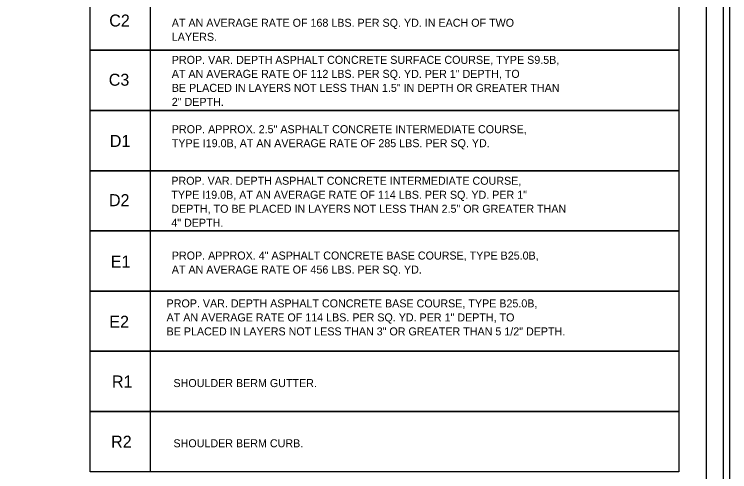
# Model space of a CAD drawing. Extents: x 573732 to 574187, y -53389 to -53257.
# Drawn here: x 573921.8 to 573984.3, y -53336 to -53296 of the extents above; entities that cross this region are included whole.
import ezdxf

# ---------------------------------------------------------------- set-up
doc = ezdxf.new("R2010")
doc.units = 0
for name, color, linetype in [('Old_Level_19', 7, 'Continuous'), ('Old_Level_21', 7, 'Continuous'), ('Sheet Plot Border Inside CELL', 7, 'Continuous'), ('Sheet Plot Border Outside CELL', 7, 'Continuous'), ('Sheet Typical CELL', 7, 'Continuous')]:
    doc.layers.add(name, color=color, linetype=linetype)

msp = doc.modelspace()

# ---------------------------------------------------------------- linework, layer by layer
at = {"layer": 'Old_Level_19'}
for points in [[(573933.675, -53299.156), (573928.412, -53299.156), (573928.412, -53293.893), (573979.867, -53293.893), (573979.867, -53299.156), (573933.675, -53299.156), (573933.675, -53293.893)], [(573933.675, -53304.419), (573928.412, -53304.419), (573928.412, -53299.156), (573979.867, -53299.156), (573979.867, -53304.419), (573933.675, -53304.419), (573933.675, -53299.156)], [(573933.675, -53309.683), (573928.412, -53309.683), (573928.412, -53304.419), (573979.867, -53304.419), (573979.867, -53309.683), (573933.675, -53309.683), (573933.675, -53304.419)], [(573933.675, -53314.944), (573928.412, -53314.944), (573928.412, -53309.682), (573979.867, -53309.682), (573979.867, -53314.944), (573933.675, -53314.944), (573933.675, -53309.682)], [(573933.675, -53320.206), (573928.412, -53320.206), (573928.412, -53314.944), (573979.867, -53314.944), (573979.867, -53320.206), (573933.675, -53320.206), (573933.675, -53314.944)], [(573933.675, -53325.469), (573928.412, -53325.469), (573928.412, -53320.206), (573979.867, -53320.206), (573979.867, -53325.469), (573933.675, -53325.469), (573933.675, -53320.206)], [(573933.675, -53330.731), (573928.412, -53330.731), (573928.412, -53325.469), (573979.867, -53325.469), (573979.867, -53330.731), (573933.675, -53330.731), (573933.675, -53325.469)], [(573933.675, -53335.994), (573928.412, -53335.994), (573928.412, -53330.731), (573979.867, -53330.731), (573979.867, -53335.994), (573933.675, -53335.994), (573933.675, -53330.731)]]:
    msp.add_lwpolyline(points, dxfattribs=at)
at = {"layer": 'Sheet Plot Border Inside CELL'}
msp.add_lwpolyline([(573983.762, -53259.642), (573783.782, -53259.642), (573783.782, -53386.254), (573983.762, -53386.254)], close=True, dxfattribs=at)
at = {"layer": 'Sheet Plot Border Outside CELL'}
msp.add_lwpolyline([(573984.302, -53256.948), (573782.222, -53256.948), (573782.222, -53388.948), (573984.302, -53388.948)], close=True, dxfattribs=at)
at = {"layer": 'Sheet Typical CELL'}
msp.add_lwpolyline([(573982.262, -53259.948), (573802.262, -53259.948), (573802.262, -53385.948), (573982.262, -53385.948)], close=True, dxfattribs=at)

# ---------------------------------------------------------------- texts
at = {"layer": 'Old_Level_21'}
for s, height, p in [('C2', 1.0505, (573930.085, -53297.083)), ('AT AN AVERAGE RATE OF 168 LBS. PER SQ. YD. IN EACH OF TWO', 0.70001, (573935.55, -53297.103)), ('LAYERS.', 0.7, (573935.55, -53298.328)), ('PROP. VAR. DEPTH ASPHALT CONCRETE SURFACE COURSE, TYPE S9.5B,', 0.70001, (573935.55, -53300.344)), ('C3', 1.0505, (573930.041, -53302.258)), ('AT AN AVERAGE RATE OF 112 LBS. PER SQ. YD. PER 1" DEPTH, TO', 0.70001, (573935.55, -53301.568)), ('BE PLACED IN LAYERS NOT LESS THAN 1.5" IN DEPTH OR GREATER THAN', 0.70001, (573935.55, -53302.793)), ('2" DEPTH.', 0.7, (573935.55, -53304.018)), ('PROP. APPROX. 2.5" ASPHALT CONCRETE INTERMEDIATE COURSE,', 0.70001, (573935.55, -53306.406)), ('D1', 1.0505, (573930.132, -53307.61)), ('TYPE I19.0B, AT AN AVERAGE RATE OF 285 LBS. PER SQ. YD.', 0.70001, (573935.55, -53307.63)), ('PROP. VAR. DEPTH ASPHALT CONCRETE INTERMEDIATE COURSE,', 0.70001, (573935.509, -53310.913)), ('D2', 1.0505, (573930.057, -53312.785)), ('TYPE I19.0B, AT AN AVERAGE RATE OF 114 LBS. PER SQ. YD. PER 1"', 0.70001, (573935.509, -53312.138)), ('DEPTH, TO BE PLACED IN LAYERS NOT LESS THAN 2.5" OR GREATER THAN', 0.70001, (573935.509, -53313.362)), ('4" DEPTH.', 0.7, (573935.509, -53314.587)), ('PROP. APPROX. 4" ASPHALT CONCRETE BASE COURSE, TYPE B25.0B,', 0.70001, (573935.55, -53317.45)), ('E1', 1.0505, (573930.216, -53318.149)), ('AT AN AVERAGE RATE OF 456 LBS. PER SQ. YD.', 0.70001, (573935.55, -53318.675)), ('PROP. VAR. DEPTH ASPHALT CONCRETE BASE COURSE, TYPE B25.0B,', 0.70001, (573935.094, -53321.632)), ('E2', 1.0505, (573930.09, -53323.412)), ('AT AN AVERAGE RATE OF 114 LBS. PER SQ. YD. PER 1" DEPTH, TO', 0.70001, (573935.094, -53322.857)), ('BE PLACED IN LAYERS NOT LESS THAN 3" OR GREATER THAN 5 1/2" DEPTH.', 0.70001, (573935.094, -53324.081)), ('R1', 1.0505, (573930.321, -53328.635)), ('SHOULDER BERM GUTTER.', 0.70001, (573935.697, -53328.598)), ('R2', 1.0505, (573930.246, -53333.898)), ('SHOULDER BERM CURB.', 0.70001, (573935.697, -53333.86))]:
    msp.add_text(s, height=height, dxfattribs=at).set_placement(p)

doc.saveas('drawing.dxf')
